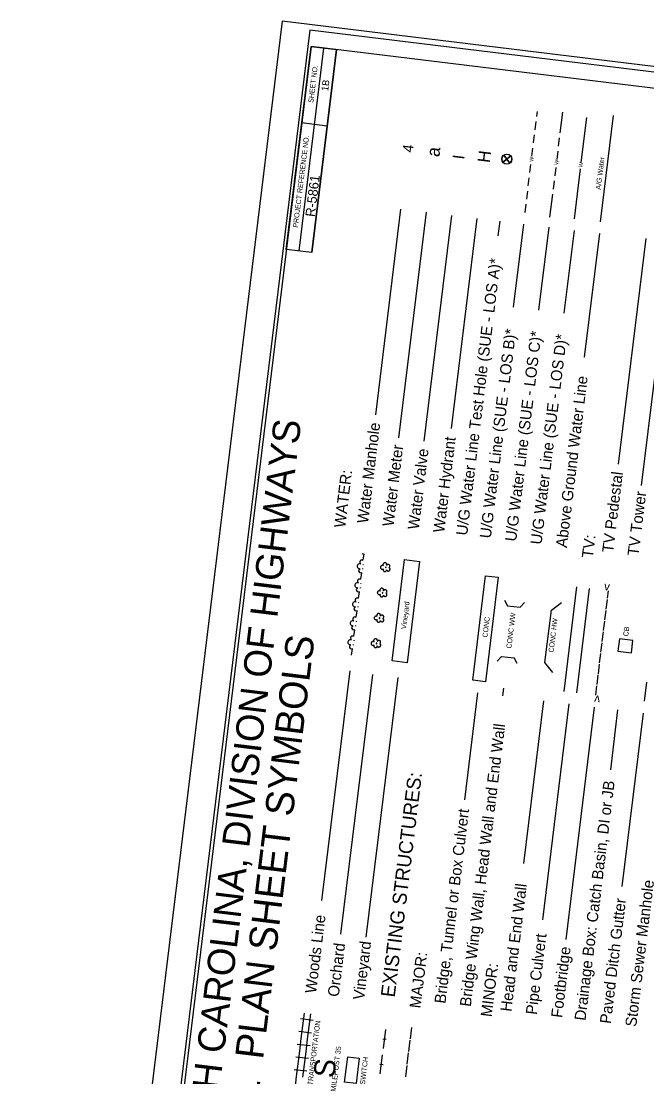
# Model space of a CAD drawing. Extents: x 480781 to 482077, y 490810 to 492615.
# Drawn here: x 480781 to 481270, y 491789 to 492615 of the extents above; entities that cross this region are included whole.
import ezdxf

# ---------------------------------------------------------------- set-up
doc = ezdxf.new("R2010")
doc.units = 0
for name, color, linetype in [('Prop XS SS Elevation Text', 7, 'Continuous'), ('Sheet Cutting Line CELL', 7, 'Continuous'), ('Sheet Data Field CELL', 7, 'Continuous'), ('Sheet Plot Border Inside CELL', 7, 'Continuous'), ('Sheet Plot Border Outside CELL', 7, 'Continuous'), ('Sheet Symbology CELL', 7, 'Continuous')]:
    doc.layers.add(name, color=color, linetype=linetype)

msp = doc.modelspace()

# ---------------------------------------------------------------- linework, layer by layer
at = {"layer": 'Prop XS SS Elevation Text'}
for points in [[(481158.23, 492510.44), (481163.16, 492504.15), (481160.7, 492507.29), (481157.55, 492504.83), (481163.84, 492509.76)], [(481157.55, 492504.83), (481160.7, 492507.29), (481158.23, 492510.44)], [(481163.84, 492509.76), (481160.7, 492507.29), (481163.16, 492504.15)]]:
    msp.add_lwpolyline(points, dxfattribs=at)
msp.add_circle((481160.7, 492507.29), 4, dxfattribs=at)
for start, end in [(128.03651, 218.03651), (308.03651, 38.03651)]:
    msp.add_arc((481160.7, 492507.29), 4, start, end, dxfattribs=at)
at = {"layer": 'Sheet Cutting Line CELL'}
msp.add_line((480984.76, 492615.38), (480780.59, 490943.81), dxfattribs=at)
at = {"layer": 'Sheet Plot Border Inside CELL'}
msp.add_lwpolyline([(481851.77, 490826.07), (482053.81, 492480.28), (481006.5, 492608.2), (480804.45, 490953.99)], close=True, dxfattribs=at)
at = {"layer": 'Sheet Plot Border Outside CELL'}
msp.add_lwpolyline([(481872.48, 490810.45), (482076.64, 492482.02), (480984.76, 492615.38), (480780.59, 490943.81)], close=True, dxfattribs=at)
at = {"layer": 'Sheet Symbology CELL'}
for p, q in [((480998.07, 492435.4), (481017.47, 492594.26)), ((481008, 492434.19), (481027.4, 492593.05)), ((481184.15, 492540.8), (481184.62, 492544.7)), ((481202.51, 492527.97), (481204.49, 492544.16)), ((481218.91, 492504.55), (481223.24, 492539.99)), ((481234.05, 492458.07), (481244.24, 492541.46)), ((481000.27, 492535.92), (481020.13, 492533.49)), ((481182.87, 492530.37), (481183.66, 492536.82)), ((481181.6, 492519.95), (481182.39, 492526.4)), ((481201.24, 492517.55), (481202.02, 492524)), ((481180.33, 492509.53), (481181.11, 492515.98)), ((481199.96, 492507.13), (481200.75, 492513.58)), ((481178.76, 492496.72), (481179.55, 492503.18)), ((481198.4, 492494.32), (481199.19, 492500.78)), ((481213.54, 492460.58), (481218.31, 492499.59)), ((481177.49, 492486.3), (481178.28, 492492.75)), ((481197.13, 492483.9), (481197.91, 492490.35)), ((481176.22, 492475.88), (481177, 492482.33)), ((481174.94, 492465.46), (481175.73, 492471.91)), ((481194.44, 492461.93), (481196.64, 492479.93)), ((481077.6, 492468.1), (481057.91, 492306.91)), ((481097.45, 492465.68), (481075.87, 492288.95)), ((481117.3, 492463.25), (481095.72, 492286.53)), ((481137.15, 492460.83), (481117.06, 492296.26)), ((481155.11, 492458.63), (481153.71, 492447.17)), ((481173.62, 492456.37), (481165.69, 492391.48)), ((481193.47, 492453.95), (481185.54, 492389.05)), ((481213.32, 492451.52), (481205.39, 492386.63)), ((481233.17, 492449.1), (481221.33, 492352.11)), ((481269.41, 492445.16), (481247.82, 492268.43)), ((481289.26, 492442.73), (481265.94, 492251.81)), ((481048.31, 492193.22), (481048.92, 492198.18)), ((481046.49, 492178.33), (481047.1, 492183.29)), ((481047.95, 492186.16), (481048.01, 492186.66)), ((481048.38, 492189.63), (481048.44, 492190.13)), ((481046.56, 492174.75), (481046.62, 492175.24)), ((481044.67, 492163.44), (481045.28, 492168.4)), ((481046.13, 492171.27), (481046.19, 492171.77)), ((481205.44, 492090.44), (481215.44, 492172.33)), ((481215.36, 492089.23), (481225.36, 492171.12)), ((481239.53, 492163.34), (481240.25, 492169.3)), ((481044.74, 492159.86), (481044.8, 492160.35)), ((481158.91, 492161.96), (481161.25, 492157.54)), ((481161.25, 492157.54), (481171.18, 492156.33)), ((481174.51, 492160.05), (481171.18, 492156.33)), ((481195.57, 492153.98), (481203.45, 492160.14)), ((481238.49, 492154.91), (481239.4, 492162.35)), ((481042.85, 492148.55), (481043.46, 492153.51)), ((481044.31, 492156.38), (481044.37, 492156.88)), ((481190.56, 492113.03), (481195.57, 492153.98)), ((481237.46, 492146.47), (481238.37, 492153.91)), ((481042.5, 492141.49), (481042.56, 492141.99)), ((481042.92, 492144.97), (481042.98, 492145.46)), ((481236.43, 492138.03), (481237.34, 492145.48)), ((481041.04, 492133.66), (481041.64, 492138.62)), ((481235.4, 492129.59), (481236.31, 492137.04)), ((481040.68, 492126.6), (481040.74, 492127.1)), ((481041.1, 492130.08), (481041.16, 492130.57)), ((481234.37, 492121.16), (481235.28, 492128.6)), ((481039.22, 492118.77), (481039.82, 492123.74)), ((481153.06, 492114.11), (481156.4, 492117.84)), ((481156.4, 492117.84), (481166.33, 492116.62)), ((481168.67, 492112.21), (481166.33, 492116.62)), ((481233.34, 492112.72), (481234.25, 492120.16)), ((481196.73, 492105.15), (481190.56, 492113.03)), ((481232.31, 492104.28), (481233.22, 492111.73)), ((481037.71, 492106.47), (481015.76, 491926.68)), ((481055.44, 492103.74), (481030.59, 491900.31)), ((481075.29, 492101.31), (481050.45, 491897.89)), ((481231.28, 492095.84), (481232.19, 492103.29)), ((481157.66, 492086.9), (481158.39, 492092.85)), ((481230.25, 492087.41), (481231.16, 492094.85)), ((481268.4, 492082.75), (481270.22, 492097.64)), ((481137.81, 492089.33), (481127.57, 492005.53)), ((481189.42, 492083.03), (481173.86, 491955.67)), ((481209.27, 492080.6), (481188.64, 491911.67)), ((481229.12, 492078.18), (481206.88, 491896.05)), ((481247.42, 492075.94), (481241.7, 492029.09)), ((481267.28, 492073.52), (481250.67, 491937.58)), ((481001.04, 491828.63), (481002.25, 491838.55)), ((481006, 491828.02), (481007.22, 491837.95)), ((481009.09, 491832.68), (480999.16, 491833.89)), ((480999.83, 491818.7), (481001.04, 491828.63)), ((481004.79, 491818.1), (481006, 491828.02)), ((481085.18, 491818.35), (481086.27, 491827.28)), ((481007.88, 491822.76), (480997.95, 491823.97)), ((480998.62, 491808.78), (480999.83, 491818.7)), ((481064.11, 491810.85), (481065.93, 491825.74)), ((481006.67, 491812.83), (480996.74, 491814.04)), ((481003.58, 491808.17), (481004.79, 491818.1)), ((481063.78, 491818.45), (481066.26, 491818.14)), ((481083.97, 491808.43), (481085.06, 491817.36)), ((481005.45, 491802.9), (480995.53, 491804.12)), ((480997.4, 491798.85), (480998.62, 491808.78)), ((481002.37, 491798.24), (481003.58, 491808.17)), ((481061.69, 491791), (481063.51, 491805.89)), ((481082.75, 491798.5), (481083.84, 491807.43)), ((481004.24, 491792.98), (480994.32, 491794.19)), ((480996.19, 491788.92), (480997.4, 491798.85)), ((481001.15, 491788.32), (481002.37, 491798.24)), ((481061.36, 491798.59), (481063.84, 491798.29)), ((481081.54, 491788.57), (481082.63, 491797.51)), ((480994.98, 491779), (480996.19, 491788.92))]:
    msp.add_line(p, q, dxfattribs=at)
for points in [[(481007.51, 492595.48), (480825.66, 491106.54), (481866.9, 490979.37), (482048.76, 492468.3)], [(480988.11, 492436.62), (481007.51, 492595.48), (481027.4, 492593.05), (481008, 492434.19)], [(481258.24, 492120.7), (481259.41, 492130.24), (481248.85, 492131.53), (481247.68, 492121.99)], [(481033.71, 491784.34), (481036.14, 491804.19), (481045.17, 491803.09), (481042.74, 491783.24)]]:
    msp.add_lwpolyline(points, close=True, dxfattribs=at)
for points in [[(481068.56, 492187.25), (481068.98, 492187.81), (481069.12, 492188.09), (481069.2, 492188.38), (481069.19, 492188.69), (481069.12, 492188.95), (481069, 492189.22), (481068.84, 492189.49), (481068.61, 492189.67), (481068.37, 492189.8), (481068.08, 492189.93), (481067.78, 492189.92), (481067.48, 492189.91), (481067.15, 492189.74), (481066.94, 492189.62), (481066.76, 492189.39), (481066.57, 492189.11), (481066.66, 492189.4), (481066.7, 492189.75), (481066.63, 492190.01), (481066.52, 492190.32), (481066.4, 492190.59), (481066.18, 492190.82), (481065.9, 492191.01), (481065.61, 492191.09), (481065.31, 492191.18), (481065.01, 492191.16), (481064.7, 492191.1), (481064.43, 492190.93), (481064.15, 492190.71), (481063.97, 492190.48), (481063.84, 492190.2), (481063.75, 492189.91), (481063.71, 492189.61), (481063.78, 492189.3), (481063.89, 492189.03), (481064.06, 492188.76)], [(481070.84, 492114.34), (481080.54, 492193.75), (481092.45, 492192.3), (481082.75, 492112.89), (481070.84, 492114.34)], [(481064.06, 492188.76), (481063.78, 492188.95), (481063.49, 492189.03), (481063.19, 492189.02), (481062.88, 492189.01), (481062.62, 492188.89), (481062.35, 492188.77), (481062.12, 492188.54), (481061.94, 492188.31), (481061.8, 492187.98), (481061.77, 492187.73), (481061.78, 492187.43), (481061.85, 492187.12), (481061.97, 492186.85), (481062.13, 492186.58), (481062.41, 492186.39), (481062.65, 492186.26), (481062.94, 492186.18), (481063.24, 492186.14), (481063.54, 492186.15), (481063.81, 492186.27), (481064.13, 492186.44), (481063.95, 492186.21), (481063.87, 492185.91), (481063.83, 492185.62), (481063.9, 492185.36), (481063.97, 492185.1), (481064.14, 492184.82), (481064.31, 492184.6), (481064.54, 492184.42), (481064.78, 492184.34), (481065.12, 492184.25), (481065.38, 492184.27), (481065.64, 492184.34), (481065.91, 492184.51), (481066.13, 492184.63), (481066.31, 492184.86), (481066.49, 492185.14), (481066.57, 492185.38), (481066.61, 492185.68), (481066.68, 492185.42), (481066.84, 492185.15), (481067.03, 492184.97), (481067.31, 492184.84), (481067.6, 492184.7), (481067.84, 492184.67), (481068.15, 492184.69), (481068.41, 492184.8), (481068.68, 492184.92), (481068.9, 492185.1), (481069.08, 492185.33), (481069.21, 492185.56), (481069.25, 492185.86), (481069.29, 492186.16), (481069.27, 492186.41), (481069.1, 492186.69), (481068.98, 492186.95), (481068.56, 492187.25)], [(481065.7, 492187.71), (481065.68, 492187.56), (481065.72, 492187.45), (481065.75, 492187.35), (481065.9, 492187.33), (481066, 492187.32), (481066.11, 492187.4), (481066.13, 492187.55), (481066.14, 492187.65), (481066.06, 492187.76), (481065.91, 492187.83), (481065.81, 492187.79), (481065.7, 492187.71)], [(481133.97, 492099.17), (481143.97, 492181.06), (481153.9, 492179.85), (481143.9, 492097.95), (481133.97, 492099.17)], [(481061.64, 492168.91), (481061.36, 492169.09), (481061.07, 492169.18), (481060.76, 492169.17), (481060.46, 492169.15), (481060.19, 492169.03), (481059.93, 492168.92), (481059.7, 492168.69), (481059.52, 492168.46), (481059.38, 492168.13), (481059.35, 492167.88), (481059.36, 492167.58), (481059.42, 492167.27), (481059.54, 492167), (481059.71, 492166.73), (481059.99, 492166.54), (481060.22, 492166.41), (481060.52, 492166.33), (481060.81, 492166.29), (481061.12, 492166.3), (481061.38, 492166.42), (481061.71, 492166.58), (481061.53, 492166.35), (481061.44, 492166.06), (481061.4, 492165.76), (481061.47, 492165.5), (481061.54, 492165.24), (481061.71, 492164.97), (481061.89, 492164.75), (481062.12, 492164.57), (481062.36, 492164.49), (481062.7, 492164.4), (481062.95, 492164.42), (481063.21, 492164.49), (481063.49, 492164.65), (481063.7, 492164.78), (481063.88, 492165.01), (481064.07, 492165.29), (481064.15, 492165.53), (481064.18, 492165.83), (481064.25, 492165.57), (481064.42, 492165.29), (481064.6, 492165.12), (481064.89, 492164.99), (481065.17, 492164.85), (481065.42, 492164.82), (481065.72, 492164.83), (481065.99, 492164.95), (481066.26, 492165.07), (481066.48, 492165.24), (481066.66, 492165.47), (481066.79, 492165.71), (481066.82, 492166.01), (481066.86, 492166.31), (481066.84, 492166.56), (481066.67, 492166.83), (481066.55, 492167.1), (481066.14, 492167.4)], [(481066.14, 492167.4), (481066.56, 492167.96), (481066.69, 492168.24), (481066.78, 492168.53), (481066.77, 492168.84), (481066.7, 492169.1), (481066.58, 492169.36), (481066.41, 492169.64), (481066.18, 492169.81), (481065.94, 492169.94), (481065.66, 492170.08), (481065.36, 492170.07), (481065.05, 492170.05), (481064.73, 492169.89), (481064.51, 492169.77), (481064.33, 492169.54), (481064.15, 492169.26), (481064.23, 492169.55), (481064.28, 492169.9), (481064.21, 492170.16), (481064.1, 492170.47), (481063.98, 492170.74), (481063.75, 492170.97), (481063.47, 492171.15), (481063.18, 492171.24), (481062.89, 492171.32), (481062.59, 492171.31), (481062.28, 492171.25), (481062, 492171.08), (481061.73, 492170.86), (481061.55, 492170.63), (481061.41, 492170.35), (481061.32, 492170.06), (481061.29, 492169.76), (481061.35, 492169.45), (481061.47, 492169.18), (481061.64, 492168.91)], [(481063.27, 492167.85), (481063.25, 492167.7), (481063.29, 492167.6), (481063.33, 492167.49), (481063.48, 492167.48), (481063.58, 492167.46), (481063.69, 492167.55), (481063.71, 492167.7), (481063.72, 492167.8), (481063.63, 492167.91), (481063.49, 492167.98), (481063.38, 492167.94), (481063.27, 492167.85)], [(481059.21, 492149.06), (481058.93, 492149.24), (481058.64, 492149.33), (481058.34, 492149.31), (481058.03, 492149.3), (481057.77, 492149.18), (481057.5, 492149.06), (481057.27, 492148.84), (481057.09, 492148.61), (481056.95, 492148.27), (481056.92, 492148.03), (481056.93, 492147.72), (481057, 492147.41), (481057.12, 492147.15), (481057.28, 492146.87), (481057.56, 492146.69), (481057.8, 492146.56), (481058.09, 492146.47), (481058.39, 492146.44), (481058.69, 492146.45), (481058.96, 492146.57), (481059.28, 492146.73), (481059.1, 492146.5), (481059.02, 492146.21), (481058.98, 492145.91), (481059.05, 492145.65), (481059.12, 492145.39), (481059.29, 492145.12), (481059.46, 492144.9), (481059.69, 492144.72), (481059.93, 492144.64), (481060.27, 492144.54), (481060.53, 492144.56), (481060.79, 492144.63), (481061.06, 492144.8), (481061.28, 492144.93), (481061.46, 492145.16), (481061.64, 492145.43), (481061.72, 492145.68), (481061.76, 492145.97), (481061.83, 492145.71), (481062, 492145.44), (481062.18, 492145.27), (481062.46, 492145.13), (481062.75, 492145), (481063, 492144.97), (481063.3, 492144.98), (481063.57, 492145.1), (481063.83, 492145.22), (481064.05, 492145.39), (481064.23, 492145.62), (481064.36, 492145.86), (481064.4, 492146.16), (481064.44, 492146.45), (481064.42, 492146.71), (481064.25, 492146.98), (481064.13, 492147.25), (481063.71, 492147.55)], [(481063.71, 492147.55), (481064.13, 492148.1), (481064.27, 492148.39), (481064.36, 492148.68), (481064.34, 492148.98), (481064.27, 492149.24), (481064.15, 492149.51), (481063.99, 492149.78), (481063.76, 492149.96), (481063.52, 492150.09), (481063.23, 492150.23), (481062.93, 492150.21), (481062.63, 492150.2), (481062.3, 492150.04), (481062.09, 492149.91), (481061.91, 492149.68), (481061.72, 492149.4), (481061.81, 492149.7), (481061.85, 492150.04), (481061.78, 492150.3), (481061.67, 492150.62), (481061.55, 492150.89), (481061.33, 492151.11), (481061.05, 492151.3), (481060.76, 492151.39), (481060.47, 492151.47), (481060.16, 492151.46), (481059.85, 492151.4), (481059.58, 492151.23), (481059.3, 492151.01), (481059.12, 492150.78), (481058.99, 492150.49), (481058.9, 492150.2), (481058.86, 492149.9), (481058.93, 492149.59), (481059.04, 492149.33), (481059.21, 492149.06)], [(481060.85, 492148), (481060.83, 492147.85), (481060.87, 492147.75), (481060.9, 492147.64), (481061.05, 492147.62), (481061.15, 492147.61), (481061.26, 492147.7), (481061.28, 492147.85), (481061.29, 492147.95), (481061.21, 492148.06), (481061.06, 492148.12), (481060.96, 492148.09), (481060.85, 492148)], [(481056.79, 492129.2), (481056.51, 492129.39), (481056.22, 492129.47), (481055.91, 492129.46), (481055.61, 492129.45), (481055.34, 492129.33), (481055.08, 492129.21), (481054.85, 492128.99), (481054.67, 492128.76), (481054.53, 492128.42), (481054.5, 492128.17), (481054.51, 492127.87), (481054.57, 492127.56), (481054.69, 492127.29), (481054.86, 492127.02), (481055.14, 492126.84), (481055.38, 492126.71), (481055.67, 492126.62), (481055.96, 492126.58), (481056.27, 492126.6), (481056.53, 492126.72), (481056.86, 492126.88), (481056.68, 492126.65), (481056.59, 492126.36), (481056.56, 492126.06), (481056.62, 492125.8), (481056.69, 492125.54), (481056.86, 492125.27), (481057.04, 492125.04), (481057.27, 492124.86), (481057.51, 492124.78), (481057.85, 492124.69), (481058.1, 492124.71), (481058.36, 492124.78), (481058.64, 492124.95), (481058.85, 492125.07), (481059.03, 492125.3), (481059.22, 492125.58), (481059.3, 492125.82), (481059.33, 492126.12), (481059.4, 492125.86), (481059.57, 492125.59), (481059.75, 492125.42), (481060.04, 492125.28), (481060.32, 492125.15), (481060.57, 492125.11), (481060.87, 492125.13), (481061.14, 492125.25), (481061.41, 492125.37), (481061.63, 492125.54), (481061.81, 492125.77), (481061.94, 492126.01), (481061.97, 492126.3), (481062.01, 492126.6), (481061.99, 492126.86), (481061.82, 492127.13), (481061.71, 492127.39), (481061.29, 492127.7)], [(481061.29, 492127.7), (481061.71, 492128.25), (481061.84, 492128.54), (481061.93, 492128.83), (481061.92, 492129.13), (481061.85, 492129.39), (481061.73, 492129.66), (481061.56, 492129.93), (481061.33, 492130.11), (481061.1, 492130.24), (481060.81, 492130.37), (481060.51, 492130.36), (481060.2, 492130.35), (481059.88, 492130.19), (481059.66, 492130.06), (481059.48, 492129.83), (481059.3, 492129.55), (481059.38, 492129.84), (481059.43, 492130.19), (481059.36, 492130.45), (481059.25, 492130.77), (481059.13, 492131.03), (481058.9, 492131.26), (481058.62, 492131.45), (481058.33, 492131.53), (481058.04, 492131.62), (481057.74, 492131.61), (481057.43, 492131.54), (481057.15, 492131.38), (481056.88, 492131.16), (481056.7, 492130.93), (481056.56, 492130.64), (481056.47, 492130.35), (481056.44, 492130.05), (481056.5, 492129.74), (481056.62, 492129.48), (481056.79, 492129.2)], [(481058.42, 492128.15), (481058.4, 492128), (481058.44, 492127.89), (481058.48, 492127.79), (481058.63, 492127.77), (481058.73, 492127.76), (481058.84, 492127.85), (481058.86, 492127.99), (481058.87, 492128.09), (481058.78, 492128.2), (481058.64, 492128.27), (481058.53, 492128.23), (481058.42, 492128.15)]]:
    msp.add_lwpolyline(points, dxfattribs=at)
for centre, radius, start, end in [((481047.11, 492191.8), 1.58, 43.80499, 244.60156), ((481048.08, 492199.74), 1.58, 239.28753, 286.7855), ((481045.7, 492188.45), 2.06, 69.00027, 277.07276), ((481046.27, 492184.85), 1.58, 101.47146, 302.26803), ((481043.88, 492173.56), 2.06, 69.00027, 277.07276), ((481045.3, 492176.91), 1.58, 43.80499, 244.60156), ((481044.45, 492169.96), 1.58, 101.47146, 302.26803), ((481042.06, 492158.67), 2.06, 69.00027, 277.07276), ((481043.48, 492162.02), 1.58, 43.80499, 244.60156), ((481042.63, 492155.07), 1.58, 101.47146, 302.26803), ((481040.24, 492143.78), 2.06, 69.00027, 277.07276), ((481040.81, 492140.18), 1.58, 101.47146, 302.26803), ((481041.66, 492147.13), 1.58, 43.80499, 244.60156), ((481039.84, 492132.25), 1.58, 43.80499, 244.60156), ((481038.42, 492128.89), 2.06, 69.00027, 277.07276), ((481038.99, 492125.3), 1.58, 101.47146, 302.26803)]:
    msp.add_arc(centre, radius, start, end, dxfattribs=at)

# ---------------------------------------------------------------- texts
at = {"layer": 'Sheet Data Field CELL'}
for s, height, rotation, p in [('1B', 5.4, 83.03651, (481020.88, 492560.35)), ('R-5861', 7.5, 83.03652, (481010.42, 492461.77))]:
    msp.add_text(s, height=height, rotation=rotation, dxfattribs=at).set_placement(p)
at = {"layer": 'Sheet Symbology CELL'}
for s, height, rotation, p in [('SHEET NO.', 4, 83.03651, (481009.19, 492551.19)), ('PROJECT REFERENCE NO.', 4, 83.03651, (480997.17, 492453.41)), ('4', 8.25, 83.03651, (481087.13, 492512.16)), ('a', 10.2, 83.03653, (481107.84, 492508.65)), ('H', 9.75, 83.03651, (481147.34, 492504.05)), ('I', 9.37, 83.03651, (481127.33, 492506.68)), ('W', 3, 83.03651, (481181.29, 492505.08)), ('W', 3, 83.03651, (481200.93, 492502.68)), ('W', 3, 83.03651, (481219.97, 492500.8)), ('A/G Water', 4, 83.03651, (481234.1, 492483.18)), ('U/G Water Line Test Hole (SUE - LOS A)*', 8.75, 83.03651, (481129.58, 492212.21)), ('U/G Water Line (SUE - LOS B)*', 8.75, 83.03651, (481148.09, 492209.95)), ('U/G Water Line (SUE - LOS C)*', 8.75, 83.03651, (481167.94, 492207.53)), ('U/G Water Line (SUE - LOS D)*', 8.75, 83.03651, (481187.79, 492205.1)), ('Above Ground Water Line', 8.75, 83.03651, (481207.65, 492202.68)), ('STATE OF NORTH CAROLINA, DIVISION OF HIGHWAYS', 21.419, 83.03651, (480908.03, 491550.39)), ('Water Manhole', 8.75, 83.03651, (481052.07, 492221.68)), ('Water Hydrant', 8.75, 83.03651, (481111.63, 492214.4)), ('Water Meter', 8.75, 83.03651, (481071.92, 492219.25)), ('Water Valve', 8.75, 83.03651, (481091.78, 492216.83)), ('WATER:', 8.75, 83.03651, (481034.15, 492218.25)), ('TV Pedestal', 8.75, 83.03651, (481243.88, 492198.73)), ('TV Tower', 8.75, 83.03651, (481263.73, 492196.31)), ('TV:', 8.75, 83.03651, (481227.98, 492194.58)), ('v', 6.6, 353.27737, (481236.54, 492169.74)), ('Vineyard', 4, 83.03653, (481081.91, 492139.01)), ('CONC WW', 4, 83.03653, (481164.18, 492123.81)), ('CONC', 4, 83.03651, (481145.46, 492132.46)), ('CONC HW', 4, 83.03651, (481197.21, 492120.71)), ('CONVENTIONAL  PLAN SHEET SYMBOLS', 22.0323, 83.03651, (480939.67, 491554.72)), ('CB', 4, 83.03651, (481255.62, 492133.36)), ('v', 6.6, 172.79566, (481233.96, 492086.94)), ('Bridge Wing Wall, Head Wall and End Wall', 8.75, 83.03651, (481132.48, 491843.2)), ('EXISTING STRUCTURES:', 11, 83.03651, (481072.92, 491850.47)), ('Drainage Box: Catch Basin, DI or JB', 8.75, 83.03651, (481222.23, 491832.25)), ('Bridge, Tunnel or Box Culvert', 8.75, 83.03651, (481112.63, 491845.62)), ('Storm Sewer Manhole', 8.75, 83.03651, (481261.95, 491827.4)), ('Head and End Wall', 8.75, 83.03651, (481164.24, 491839.32)), ('Paved Ditch Gutter', 8.75, 83.03651, (481242.1, 491829.82)), ('Woods Line', 8.75, 83.03651, (481011.39, 491853.63)), ('Orchard', 8.75, 83.03651, (481029.12, 491850.9)), ('Vineyard', 8.75, 83.03651, (481048.97, 491848.48)), ('Pipe Culvert', 8.75, 83.03651, (481184.08, 491836.89)), ('MAJOR:', 8.75, 83.03651, (481093.15, 491841.93)), ('Footbridge', 8.75, 83.03651, (481203.93, 491834.48)), ('MINOR:', 8.75, 83.03651, (481148.86, 491835.13)), ('CSX TRANSPORTATION', 4, 83.03651, (481007.1, 491769.02)), ('MILEPOST 35', 4, 83.03651, (481026.77, 491776.88)), ('SWITCH', 4, 83.03651, (481049.6, 491782.35)), ('S', 16.5, 83.03651, (481025.58, 491787.11))]:
    msp.add_text(s, height=height, rotation=rotation, dxfattribs=at).set_placement(p)

doc.saveas('drawing.dxf')
